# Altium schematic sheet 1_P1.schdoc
size 307 x 218 mm; Symbol: Drawing-Symbol_A4; Device: Drawing-Symbol_A4; @Project Name: PPTC SMD research; @Page Count: 1; @Update Date: 2026-07-04; @Create Date: 2026-07-04; @Schematic Name: Schematic1; @Page No: 1; @Page Name: P1; Company: EasyEDA.com; Version: V1.0; Page Size: A4; @Create Time: 11:02:04; @Update Time: 13:02:04; Width: 1170; Height: 825; Region Start: 1; X Region Count: 6; Y Region Count: 4; Blade Width: 10; Title Block Position: 3; @Board Name: Board1
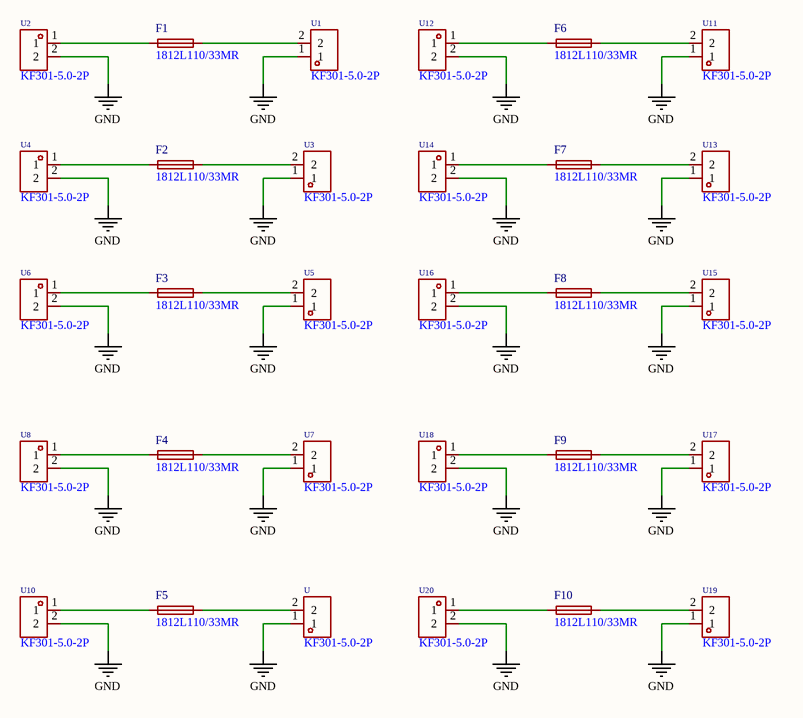
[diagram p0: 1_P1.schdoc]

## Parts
F1  1812L110/33MR  [F1812]
F2  1812L110/33MR  [F1812]
F3  1812L110/33MR  [F1812]
F4  1812L110/33MR  [F1812]
F5  1812L110/33MR  [F1812]
F6  1812L110/33MR  [F1812]
F7  1812L110/33MR  [F1812]
F8  1812L110/33MR  [F1812]
F9  1812L110/33MR  [F1812]
F10  1812L110/33MR  [F1812]
U  KF301-5.0-2P  [CONN-TH_P5.00_KF301-5.0-2P]
U1  KF301-5.0-2P  [CONN-TH_P5.00_KF301-5.0-2P]
U2  KF301-5.0-2P  [CONN-TH_P5.00_KF301-5.0-2P]
U3  KF301-5.0-2P  [CONN-TH_P5.00_KF301-5.0-2P]
U4  KF301-5.0-2P  [CONN-TH_P5.00_KF301-5.0-2P]
U5  KF301-5.0-2P  [CONN-TH_P5.00_KF301-5.0-2P]
U6  KF301-5.0-2P  [CONN-TH_P5.00_KF301-5.0-2P]
U7  KF301-5.0-2P  [CONN-TH_P5.00_KF301-5.0-2P]
U8  KF301-5.0-2P  [CONN-TH_P5.00_KF301-5.0-2P]
U10  KF301-5.0-2P  [CONN-TH_P5.00_KF301-5.0-2P]
U11  KF301-5.0-2P  [CONN-TH_P5.00_KF301-5.0-2P]
U12  KF301-5.0-2P  [CONN-TH_P5.00_KF301-5.0-2P]
U13  KF301-5.0-2P  [CONN-TH_P5.00_KF301-5.0-2P]
U14  KF301-5.0-2P  [CONN-TH_P5.00_KF301-5.0-2P]
U15  KF301-5.0-2P  [CONN-TH_P5.00_KF301-5.0-2P]
U16  KF301-5.0-2P  [CONN-TH_P5.00_KF301-5.0-2P]
U17  KF301-5.0-2P  [CONN-TH_P5.00_KF301-5.0-2P]
U18  KF301-5.0-2P  [CONN-TH_P5.00_KF301-5.0-2P]
U19  KF301-5.0-2P  [CONN-TH_P5.00_KF301-5.0-2P]
U20  KF301-5.0-2P  [CONN-TH_P5.00_KF301-5.0-2P]

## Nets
GND: U.1 U1.1 U2.2 U3.1 U4.2 U5.1 U6.2 U7.1 U8.2 U10.2 U11.1 U12.2 U13.1 U14.2 U15.1 U16.2 U17.1 U18.2 U19.1 U20.2
NetF1_1: F1.1 U2.1
NetF1_2: F1.2 U1.2
NetF2_1: F2.1 U4.1
NetF2_2: F2.2 U3.2
NetF3_1: F3.1 U6.1
NetF3_2: F3.2 U5.2
NetF4_1: F4.1 U8.1
NetF4_2: F4.2 U7.2
NetF5_1: F5.1 U10.1
NetF5_2: F5.2 U.2
NetF6_1: F6.1 U12.1
NetF6_2: F6.2 U11.2
NetF7_1: F7.1 U14.1
NetF7_2: F7.2 U13.2
NetF8_1: F8.1 U16.1
NetF8_2: F8.2 U15.2
NetF9_1: F9.1 U18.1
NetF9_2: F9.2 U17.2
NetF10_1: F10.1 U20.1
NetF10_2: F10.2 U19.2

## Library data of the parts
F1-F10 = 1812L110/33MR: Manufacturer: Littelfuse(美国力特); Add into BOM: yes; Voltage - Max: 33V; Current - Max: 20A; Hold Current: 1.1A; Trip Current: 1.95A; Power Dissipation: 800mW; Resistance - Initial (Ri) (Min): 60mΩ; Resistance - Post Trip (R1) (Max): 200mΩ; Time to Trip(Max): 500ms
U U1-U8 U10-U20 = KF301-5.0-2P: Manufacturer: KEFA(科发); Add into BOM: yes; Number of Positions or Pins: 1x2P; Pitch: 5mm; Number of PINs Per Row: 2; Current Rating: 17A; Voltage Rating (Max): 250V; Wire Gauge - AWG: 14~22; Wire Gauge - mm2: 1.5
